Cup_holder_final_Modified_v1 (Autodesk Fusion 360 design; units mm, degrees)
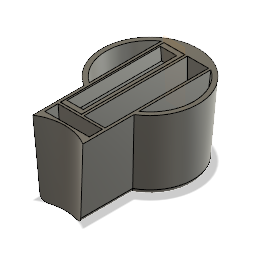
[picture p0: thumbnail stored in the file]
canvas "Canvas1"
sketch "Sketch1" plane through (0, 0, 0) normal (0, 0, 1) x axis (1, 0, 0)
  line L1 (47.1318, 100) -> (26.1306, 100)
  line L2 (42.6175, 34.4588) -> (47.1318, 100)
  line L3 (26.1306, 34.4588) -> (42.6175, 34.4588)
  line L4 (26.1306, 34.4588) -> (26.1306, 100)
  line L5 (26.1306, 34.4588) -> (9.6436, 34.4588)
  line L6 (9.6436, 34.4588) -> (5.1294, 100)
  line L7 (5.1294, 100) -> (26.1306, 100)
  line L8 (26.1306, 34.4588) -> (26.1306, 100)
  horizontal L1
  parallel L1 L3
  perpendicular L3 L4
extrude "Extrude1" new body sketch "Sketch1" along normal blind 120
sketch "Sketch2" plane through (0, 100, 0) normal (0, 1, 0) x axis (-1, 0, 0)
  line L1 (-5.1294, 0) -> (-47.1318, 0)
  line L2 (-5.1294, 120) -> (-5.1294, 0)
  line L3 (-47.1318, 120) -> (-5.1294, 120)
  line L4 (-47.1318, 0) -> (-47.1318, 120)
  circle C1 centre (-26.1306, 39) radius 39
  dimension "d5" diameter C1 = 78
sketch "Sketch3" plane through (0, 34.4588, 0) normal (0, -1, 0) x axis (1, 0, 0)
  line L1 (42.6175, 0) -> (9.6436, 0)
  line L2 (42.6175, 120) -> (42.6175, 0)
  line L3 (9.6436, 120) -> (42.6175, 120)
  line L4 (9.6436, 0) -> (9.6436, 120)
  circle C1 centre (26.1306, 39) radius 34
  point P6 (26.1306, 39)
  point P7 (26.1306, 39)
  coincident P6 P7
  dimension "d6" diameter C1 = 68
offset_faces "OffsetFaces1" distance -40
work_plane "WorkPlane1" sketch "Sketch2" AlongDistance 0
sketch "Sketch4" plane through (26.1306, 100, 96.0888) normal (0, 1, 0) x axis (1, 0, 0)
  circle C1 centre (0, 57.0888) radius 39
  point P2 (0, 57.0888)
  point P3 (0, 57.0888)
  coincident P2 P3
work_plane "WorkPlane2" sketch "Sketch3" AlongDistance 0
sketch "Sketch5" plane through (26.1306, 34.4588, 94.5038) normal (0, -1, 0) x axis (1, 0, 0)
  circle C1 centre (0, -55.5038) radius 34
  point P2 (0, -55.5038)
  point P3 (0, -55.5038)
  coincident P2 P3
loft "Loft1" sketch "Sketch5" + "Sketch4"
combine "Combine1"
sketch "Sketch7" plane through (0, 100, 0) normal (0, 1, 0) x axis (-1, 0, 0)
  line L1 (-5.1294, 120) -> (-5.1294, 71.8626)
  line L2 (-47.1318, 120) -> (-5.1294, 120)
  line L3 (-47.1318, 71.8626) -> (-47.1318, 120)
  arc A1 centre (-26.1306, 39) radius 39 clockwise from (-5.1294, 71.8626) to (-47.1318, 71.8626)
work_plane "WorkPlane3" sketch "Sketch7" AlongDistance 0
sketch "Sketch8" plane through (26.1306, 100, 60) normal (0, 1, 0) x axis (1, 0, 0)
  line L1 (1.5052, -36.3427) -> (18.4948, -36.3427)
  line L2 (1.5052, 48.6573) -> (1.5052, -36.3427)
  line L3 (18.4948, 48.6573) -> (1.5052, 48.6573)
  line L4 (18.4948, -36.3427) -> (18.4948, 48.6573)
sketch "Sketch9" plane through (26.1306, 100, 60) normal (0, 1, 0) x axis (1, 0, 0)
  line L1 (-18.4948, 48.6573) -> (-18.4948, -36.3427)
  line L2 (-1.5052, -36.3427) -> (-1.5052, 48.6573)
  line L3 (-1.5052, 48.6573) -> (-18.4948, 48.6573)
  line L4 (-1.5052, -36.3427) -> (-18.4948, -36.3427)
extrude "Extrude2" cut sketch "Sketch9" along a picked direction distance -45
extrude "Extrude3" cut sketch "Sketch8" along a picked direction distance -45
sketch "Sketch10" plane through (26.1306, 100, 60) normal (0, 1, 0) x axis (1, 0, 0)
  line L1 (1.4948, 48.6573) -> (-1.4948, 48.6573)
  line L2 (1.4948, -36.3427) -> (1.4948, 48.6573)
  line L3 (-1.4948, -36.3427) -> (1.4948, -36.3427)
  line L4 (-1.4948, 48.6573) -> (-1.4948, -36.3427)
  point P4 (1.4948, -36.3427)
  point P7 (1.4948, -36.3427)
  point P2 (-1.4948, 48.6573)
  point P6 (-1.4948, 48.6573)
  horizontal L1
  vertical L2
  horizontal L3
  vertical L4
  coincident P4 P7
  coincident P2 P6
extrude "Extrude4" add sketch "Sketch10" against normal blind 55
offset_faces "OffsetFaces2" distance -0.5
offset_faces "OffsetFaces3" distance -0.5
offset_faces "OffsetFaces4" distance -2
offset_faces "OffsetFaces5" distance -2
offset_faces "OffsetFaces6" distance 2
offset_faces "OffsetFaces7" distance 2
move_face "MoveFace1"
move_face "MoveFace2"
offset_faces "OffsetFaces8" distance 0.7
offset_faces "OffsetFaces9" distance 0.7
sketch "Sketch11" plane through (0, 0, 0) normal (0, 0, 1) x axis (1, 0, 0)
sketch "Sketch12" plane through (0, 100, 0) normal (0, 1, 0) x axis (-1, 0, 0)
  line L1 (-7.5347, 94.3427) -> (-25.1358, 94.3427)
  line L2 (-7.5347, 9.3427) -> (-7.5347, 94.3427)
  line L3 (-25.1358, 9.3427) -> (-7.5347, 9.3427)
  line L4 (-25.1358, 94.3427) -> (-25.1358, 9.3427)
  line L5 (-27.1254, 9.3427) -> (-27.1254, 94.3427)
  line L6 (-44.7264, 9.3427) -> (-27.1254, 9.3427)
  line L7 (-44.7264, 94.3427) -> (-44.7264, 9.3427)
  line L8 (-27.1254, 94.3427) -> (-44.7264, 94.3427)
  line L9 (-5.1294, 120) -> (-5.1294, 71.8626)
  line L10 (-47.1318, 120) -> (-5.1294, 120)
  line L11 (-47.1318, 71.8626) -> (-47.1318, 120)
  arc A1 centre (-26.1306, 39) radius 39 clockwise from (-5.1294, 71.8626) to (-47.1318, 71.8626)
  circle C1 centre (-26.1306, 148) radius 39
extrude "Extrude6" cut sketch "Sketch12" profile of L9 L10 L11 C1 against normal blind 555
fillet "Fillet1" radius 5
sketch "Sketch16" plane through (0, 100, 0) normal (0, 1, 0) x axis (-1, 0, 0)
  line L1 (-47.1318, 71.8626) -> (-47.1318, 115.1374)
  line L2 (-5.1294, 115.1374) -> (-5.1294, 71.8626)
  line L3 (-7.5347, 94.3427) -> (-25.1358, 94.3427)
  line L4 (-7.5347, 9.3427) -> (-7.5347, 94.3427)
  line L5 (-25.1358, 9.3427) -> (-7.5347, 9.3427)
  line L6 (-25.1358, 94.3427) -> (-25.1358, 9.3427)
  line L7 (-27.1254, 9.3427) -> (-27.1254, 94.3427)
  line L8 (-44.7264, 9.3427) -> (-27.1254, 9.3427)
  line L9 (-44.7264, 94.3427) -> (-44.7264, 9.3427)
  line L10 (-27.1254, 94.3427) -> (-44.7264, 94.3427)
  line L11 (-44.7264, 96.2296) -> (-7.5347, 96.2296)
  line L12 (-44.7264, 106.2296) -> (-44.7264, 96.2296)
  line L13 (-7.5347, 106.2296) -> (-44.7264, 106.2296)
  line L14 (-7.5347, 96.2296) -> (-7.5347, 106.2296)
  arc A1 centre (-26.1306, 148) radius 39 clockwise from (-5.1294, 115.1374) to (-47.1318, 115.1374)
  arc A2 centre (-26.1306, 39) radius 39 clockwise from (-5.1294, 71.8626) to (-47.1318, 71.8626)
  point P16 (-7.5347, 96.2296)
  point P19 (-7.5347, 106.2296)
  horizontal L11
  vertical L12
  horizontal L13
  vertical L14
  dimension "d43" distance P16 P19 = 10
work_plane "WorkPlane5" AlongDistance -50
sketch "Sketch17" plane through (26.1306, 50, 60) normal (0, 1, 0) x axis (1, 0, 0)
  line L1 (-15, -46.2296) -> (15, -46.2296)
  line L2 (-15, -36.2296) -> (-15, -46.2296)
  line L3 (15, -36.2296) -> (-15, -36.2296)
  line L4 (15, -46.2296) -> (15, -36.2296)
  line L5 (-15, -36.2296) -> (15, -46.2296)
  line L6 (15, -36.2296) -> (-15, -46.2296)
  point P6 (0, -41.2296)
  point P4 (-15, -36.2296)
  point P5 (15, -36.2296)
  perpendicular L1 L2
  parallel L1 L3
  parallel L2 L4
  horizontal L1
  coincident L5 P6
  coincident L6 P6
  dimension "d45" distance P4 P5 = 30
loft "Loft3" sketch "Sketch16" + "Sketch17"
offset_faces "OffsetFaces11" distance 0.113
offset_faces "OffsetFaces12" distance -1
sketch "Sketch18" plane through (0, 100, 0) normal (0, 1, 0) x axis (-1, 0, 0)
  line L1 (-7.5347, 107.2296) -> (-44.7264, 107.2296)
  line L2 (-7.5347, 96.3426) -> (-7.5347, 107.2296)
  line L3 (-44.7264, 96.3426) -> (-7.5347, 96.3426)
  line L4 (-44.7264, 107.2296) -> (-44.7264, 96.3426)
  line L5 (-47.1318, 71.8626) -> (-47.1318, 115.1374)
  line L6 (-5.1294, 115.1374) -> (-5.1294, 71.8626)
  line L7 (-7.5347, 94.3427) -> (-25.1358, 94.3427)
  line L8 (-7.5347, 9.3427) -> (-7.5347, 94.3427)
  line L9 (-25.1358, 9.3427) -> (-7.5347, 9.3427)
  line L10 (-25.1358, 94.3427) -> (-25.1358, 9.3427)
  line L11 (-27.1254, 9.3427) -> (-27.1254, 94.3427)
  line L12 (-44.7264, 9.3427) -> (-27.1254, 9.3427)
  line L13 (-44.7264, 94.3427) -> (-44.7264, 9.3427)
  line L14 (-27.1254, 94.3427) -> (-44.7264, 94.3427)
  line L15 (-50.1306, 39) -> (-26.1306, 39)
  line L16 (-50.1306, 11.5) -> (-50.1306, 66.5)
  line L17 (-2.1306, 39) -> (-26.1306, 39)
  line L18 (-2.1306, 11.5) -> (-2.1306, 66.5)
  arc A1 centre (-26.1306, 148) radius 39 clockwise from (-5.1294, 115.1374) to (-47.1318, 115.1374)
  arc A2 centre (-26.1306, 39) radius 39 clockwise from (-5.1294, 71.8626) to (-47.1318, 71.8626)
  arc A3 centre (-26.1306, 39) radius 36.5 clockwise from (-2.1306, 66.5) to (-2.1306, 11.5)
  arc A4 centre (-26.1306, 39) radius 36.5 clockwise from (-50.1306, 11.5) to (-50.1306, 66.5)
  point P20 (-26.1306, 39)
  point P21 (-26.1306, 39)
  point P23 (-50.1306, 66.5)
  point P25 (-26.1306, 39)
  point P22 (-50.1306, 39)
  point P26 (-2.1306, 39)
  concentric A2 A3
  coincident P20 P21
  perpendicular L13 L15
  coincident P23 A3
  perpendicular L15 L16
  coincident P20 P25
  perpendicular L8 L17
  perpendicular L17 L18
  dimension "d48" diameter A3 = 73
  dimension "d49" distance P21 P22 = 24
  dimension "d50" distance P25 P26 = 24
sketch "Sketch19" plane through (26.1306, 50, 60) normal (0, 1, 0) x axis (1, 0, 0)
  line L1 (-24, 21) -> (0, 21)
  line L2 (-23, 21) -> (0, 21)
  line L3 (23, 21) -> (0, 21)
  line L4 (-23, 41.7846) -> (-23, 0.2154)
  line L5 (23, 41.7846) -> (23, 0.2154)
  arc A1 centre (0, 21) radius 31 clockwise from (23, 41.7846) to (23, 0.2154)
  arc A2 centre (0, 21) radius 31 clockwise from (-23, 0.2154) to (-23, 41.7846)
  point P2 (0, 21)
  point P3 (0, 21)
  point P6 (0, 21)
  point P7 (-23, 21)
  point P10 (-23, 41.7846)
  point P8 (23, 21)
  coincident P2 P3
  coincident P3 P6
  coincident L1 P7
  parallel L2 L3
  coincident P10 A1
  perpendicular L1 L4
  perpendicular L3 L5
  concentric A1 A2
  dimension "d51" diameter A1 = 62
  dimension "d52" distance P6 P7 = 23
  dimension "d53" distance P6 P8 = 23
loft "Loft4" sketch "Sketch18" + "Sketch19"
loft "Loft5" sketch "Sketch18" + "Sketch19"
sketch "Sketch20" plane through (0, 100, 0) normal (0, 1, 0) x axis (-1, 0, 0)
  curve K1 (-50.1306, 66.5) -> (-50.1306, 11.5)
  line L1 (-50.1306, 11.5) -> (-50.1306, 66.5)
  curve K2 (-2.1306, 11.5) -> (-2.1306, 66.5)
  line L2 (-2.1306, 66.5) -> (-2.1306, 11.5)
  line L3 (-7.5347, 107.2296) -> (-44.7264, 107.2296)
  line L4 (-7.5347, 96.3426) -> (-7.5347, 107.2296)
  line L5 (-44.7264, 96.3426) -> (-7.5347, 96.3426)
  line L6 (-44.7264, 107.2296) -> (-44.7264, 96.3426)
  line L7 (-47.1318, 71.8626) -> (-47.1318, 115.1374)
  line L8 (-5.1294, 115.1374) -> (-5.1294, 71.8626)
  line L9 (-7.5347, 94.3427) -> (-25.1358, 94.3427)
  line L10 (-7.5347, 9.3427) -> (-7.5347, 94.3427)
  line L11 (-25.1358, 9.3427) -> (-7.5347, 9.3427)
  line L12 (-25.1358, 94.3427) -> (-25.1358, 9.3427)
  line L13 (-27.1254, 9.3427) -> (-27.1254, 94.3427)
  line L14 (-44.7264, 9.3427) -> (-27.1254, 9.3427)
  line L15 (-44.7264, 94.3427) -> (-44.7264, 9.3427)
  line L16 (-27.1254, 94.3427) -> (-44.7264, 94.3427)
  arc A1 centre (-26.1306, 148) radius 39 clockwise from (-5.1294, 115.1374) to (-47.1318, 115.1374)
  arc A2 centre (-26.1306, 39) radius 39 clockwise from (-5.1294, 71.8626) to (-47.1318, 71.8626)
sketch "Sketch21" plane through (-1.8977, 54.343, 0) normal (-0.0349, 0.9994, 0) x axis (0, 0, 1)
  line L1 (9.3427, 27.0499) -> (94.3427, 27.0499)
  line L2 (9.3427, 11.8108) -> (9.3427, 27.0499)
  line L3 (94.3427, 11.8108) -> (9.3427, 11.8108)
  line L4 (94.3427, 27.0499) -> (94.3427, 11.8108)
  line L5 (94.3427, 27.0499) -> (9.3427, 27.0499)
  line L6 (94.3427, 11.8108) -> (94.3427, 27.0499)
  line L7 (9.3427, 11.8108) -> (94.3427, 11.8108)
  line L8 (9.3427, 27.0499) -> (9.3427, 11.8108)
  point P5 (94.3427, 11.8108)
  point P8 (94.3427, 11.8108)
  point P3 (9.3427, 27.0499)
  point P6 (9.3427, 27.0499)
  horizontal L5
  vertical L6
  horizontal L7
  vertical L8
  coincident P5 P8
  coincident P3 P6
sketch "Sketch22" plane through (0, 100, 0) normal (0, 1, 0) x axis (-1, 0, 0)
  curve K1 (-50.1306, 66.5) -> (-50.1306, 11.5)
  line L1 (-50.1306, 11.5) -> (-50.1306, 66.5)
  curve K2 (-2.1306, 11.5) -> (-2.1306, 66.5)
  line L2 (-2.1306, 66.5) -> (-2.1306, 11.5)
  line L3 (-7.5347, 107.2296) -> (-44.7264, 107.2296)
  line L4 (-7.5347, 96.3426) -> (-7.5347, 107.2296)
  line L5 (-44.7264, 96.3426) -> (-7.5347, 96.3426)
  line L6 (-44.7264, 107.2296) -> (-44.7264, 96.3426)
  line L7 (-47.1318, 71.8626) -> (-47.1318, 115.1374)
  line L8 (-5.1294, 115.1374) -> (-5.1294, 71.8626)
  line L9 (-7.5347, 94.3427) -> (-25.1358, 94.3427)
  line L10 (-7.5347, 9.3427) -> (-7.5347, 94.3427)
  line L11 (-25.1358, 9.3427) -> (-7.5347, 9.3427)
  line L12 (-25.1358, 94.3427) -> (-25.1358, 9.3427)
  line L13 (-27.1254, 9.3427) -> (-27.1254, 94.3427)
  line L14 (-44.7264, 9.3427) -> (-27.1254, 9.3427)
  line L15 (-44.7264, 94.3427) -> (-44.7264, 9.3427)
  line L16 (-27.1254, 94.3427) -> (-44.7264, 94.3427)
  line L17 (-25.1358, 9.3427) -> (-7.5347, 9.3427)
  line L18 (-25.1358, 94.3427) -> (-25.1358, 9.3427)
  line L19 (-7.5347, 94.3427) -> (-25.1358, 94.3427)
  line L20 (-7.5347, 9.3427) -> (-7.5347, 94.3427)
  line L21 (-44.7264, 9.3427) -> (-27.1254, 9.3427)
  line L22 (-44.7264, 94.3427) -> (-44.7264, 9.3427)
  line L23 (-27.1254, 94.3427) -> (-44.7264, 94.3427)
  line L24 (-27.1254, 9.3427) -> (-27.1254, 94.3427)
  arc A1 centre (-26.1306, 148) radius 39 clockwise from (-5.1294, 115.1374) to (-47.1318, 115.1374)
  arc A2 centre (-26.1306, 39) radius 39 clockwise from (-5.1294, 71.8626) to (-47.1318, 71.8626)
  point P16 (-25.1358, 94.3427)
  point P26 (-25.1358, 94.3427)
  point P18 (-7.5347, 9.3427)
  point P24 (-7.5347, 9.3427)
  point P23 (-44.7264, 94.3427)
  point P30 (-44.7264, 94.3427)
  point P21 (-27.1254, 9.3427)
  point P28 (-27.1254, 9.3427)
  horizontal L17
  vertical L18
  horizontal L19
  vertical L20
  coincident P16 P26
  coincident P18 P24
  horizontal L21
  vertical L22
  horizontal L23
  vertical L24
  coincident P23 P30
  coincident P21 P28
sketch "Sketch23" plane through (1.9614, 56.1658, 0) normal (0.0349, 0.9994, 0) x axis (0, 0, -1)
  line L1 (-94.3427, -25.1794) -> (-9.3427, -25.1794)
  line L2 (-94.3427, -40.4185) -> (-94.3427, -25.1794)
  line L3 (-9.3427, -40.4185) -> (-94.3427, -40.4185)
  line L4 (-9.3427, -25.1794) -> (-9.3427, -40.4185)
  line L5 (-9.3427, -25.1794) -> (-94.3427, -25.1794)
  line L6 (-9.3427, -40.4185) -> (-9.3427, -25.1794)
  line L7 (-94.3427, -40.4185) -> (-9.3427, -40.4185)
  line L8 (-94.3427, -25.1794) -> (-94.3427, -40.4185)
  point P5 (-9.3427, -40.4185)
  point P8 (-9.3427, -40.4185)
  point P3 (-94.3427, -25.1794)
  point P6 (-94.3427, -25.1794)
  horizontal L5
  vertical L6
  horizontal L7
  vertical L8
  coincident P5 P8
  coincident P3 P6
loft "Loft6" sketch "Sketch20" + "Sketch21" bodies "Insert 1"
loft "Loft7" sketch "Sketch22" + "Sketch23" bodies "Insert 2"
offset_faces "OffsetFaces13" distance -0.1
offset_faces "OffsetFaces14" distance -0.1
offset_faces "OffsetFaces15" distance -0.1
offset_faces "OffsetFaces16" distance -0.1
offset_faces "OffsetFaces17" distance -0.1
shell "Shell1" innerThickness 2
move_face "MoveFace3"
move_face "MoveFace4"
sketch "Sketch24" plane through (0, 0, 9.4427) normal (0, 0, -1) x axis (-1, 0, 0)
  line L1 (-25.0358, 100) -> (-7.6349, 100)
  line L2 (-25.0358, 55.3836) -> (-25.0358, 100)
  line L3 (-10.0006, 54.8586) -> (-25.0358, 55.3836)
  line L4 (-7.6349, 100) -> (-10.0006, 54.8586)
offset_faces "OffsetFaces18" distance -0.4
extrude "Extrude7" add of existing geometry blind 3
extrude "Extrude8" add of existing geometry blind 3
extrude "Extrude9" cut of existing geometry blind -1
extrude "Extrude10" cut of existing geometry blind -1
offset_faces "OffsetFaces19" distance 1
sketch "Sketch25" plane through (0, 0, 94.2427) normal (0, 0, 1) x axis (1, 0, 0)
  line L1 (7.6349, 100) -> (25.0358, 100)
  line L2 (10.0006, 54.8586) -> (7.6349, 100)
  line L3 (25.0358, 55.3836) -> (10.0006, 54.8586)
  line L4 (25.0358, 100) -> (25.0358, 55.3836)
  line L5 (14, 90) -> (14, 100)
  line L6 (27.5208, 90) -> (5, 90)
  point P6 (14, 100)
  coincident L1 P6
  perpendicular L1 L5
  perpendicular L4 L6
split "Split1" bodies "Insert 1 (1)"
offset_faces "OffsetFaces20" distance -0.5
sketch "Sketch26" plane through (0, 0, 107.2296) normal (0, 0, -1) x axis (-1, 0, 0)
  line L1 (-44.7264, 100) -> (-7.5347, 100)
  line L2 (-41.1306, 50) -> (-44.7264, 100)
  line L3 (-11.1306, 50) -> (-41.1306, 50)
  line L4 (-7.5347, 100) -> (-11.1306, 50)
  line L5 (28.4654, 95) -> (-25.1358, 95)
split "Split2" bodies "Insert_Mod", "Holder_Mod"
offset_faces "OffsetFaces21" distance 1
offset_faces "OffsetFaces22" distance 5
offset_faces "OffsetFaces23" distance -3.5
offset_faces "OffsetFaces24" distance -3.5
extrude "Extrude5" cut sketch "Sketch12" profile of L9 L10 L11 C1 against normal blind 98
sketch "Sketch13" plane through (0, 100, 0) normal (0, 1, 0) x axis (-1, 0, 0)
  line L1 (-46.6306, 72.1776) -> (-46.6306, 119.8224)
  line L2 (-5.6306, 119.8224) -> (-5.6306, 72.1776)
  line L3 (-7.5347, 94.3427) -> (-25.1358, 94.3427)
  line L4 (-7.5347, 9.3427) -> (-7.5347, 94.3427)
  line L5 (-25.1358, 9.3427) -> (-7.5347, 9.3427)
  line L6 (-25.1358, 94.3427) -> (-25.1358, 9.3427)
  line L7 (-27.1254, 9.3427) -> (-27.1254, 94.3427)
  line L8 (-44.7264, 9.3427) -> (-27.1254, 9.3427)
  line L9 (-44.7264, 94.3427) -> (-44.7264, 9.3427)
  line L10 (-27.1254, 94.3427) -> (-44.7264, 94.3427)
  line L11 (-44.7264, 96.507) -> (-7.5347, 96.507)
  line L12 (-44.7264, 112.007) -> (-44.7264, 96.507)
  line L13 (-7.5347, 112.007) -> (-44.7264, 112.007)
  line L14 (-7.5347, 96.507) -> (-7.5347, 112.007)
  arc A1 centre (-26.1306, 153) radius 39 clockwise from (-5.6306, 119.8224) to (-46.6306, 119.8224)
  arc A2 centre (-26.1306, 39) radius 39 clockwise from (-5.6306, 72.1776) to (-46.6306, 72.1776)
  point P16 (-7.5347, 96.507)
  point P19 (-7.5347, 112.007)
  horizontal L11
  vertical L12
  horizontal L13
  vertical L14
  dimension "d36" distance P16 P19 = 15.5
work_plane "WorkPlane4" sketch "Sketch13" AlongDistance -50
sketch "Sketch14" plane through (26.1306, 50, 59.9112) normal (0, 1, 0) x axis (1, 0, 0)
sketch "Sketch15" plane through (26.1306, 50, 59.9112) normal (0, 1, 0) x axis (1, 0, 0)
  line L1 (-15, -52.0957) -> (15, -52.0957)
  line L2 (-15, -36.5957) -> (-15, -52.0957)
  line L3 (15, -36.5957) -> (-15, -36.5957)
  line L4 (15, -52.0957) -> (15, -36.5957)
  line L5 (-15, -36.5957) -> (15, -52.0957)
  line L6 (15, -36.5957) -> (-15, -52.0957)
  point P6 (0, -44.3457)
  point P4 (-15, -36.5957)
  point P5 (15, -36.5957)
  perpendicular L1 L2
  parallel L1 L3
  parallel L2 L4
  horizontal L1
  coincident L5 P6
  coincident L6 P6
  dimension "d38" distance P4 P5 = 30
loft "Loft2" sketch "Sketch13" + "Sketch15"
offset_faces "OffsetFaces10" distance -0.164
named bodies: "Holder", "Insert 1", "Insert 2", "Insert 1 (1)", "Insert_Mod", "Holder_Mod"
